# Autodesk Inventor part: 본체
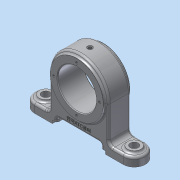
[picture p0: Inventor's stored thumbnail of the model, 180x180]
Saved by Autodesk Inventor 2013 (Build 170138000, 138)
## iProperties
Created: 2019-05
Part Number: 본체
Material: 알루미늄 6061
Document SubType Name: Modeling
Designer: dgall
Density: 2.71 g/cm^3
Mass: 457.09 g
Surface Area: 318.147 cm^2
Volume: 168.668 cm^3
Author: dgall
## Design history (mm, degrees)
sketch "스케치1"
  geometry: L1 (0, 0)-(0, 60); C1 r 40 at (0, 60)
  constraints: 2 end point, 1 centre point, 1 coincident, 1 vertical
  dimensions: "d0" = 60 distance of L1.start L1.end; "d1" = 80 diameter of C1
extrude "돌출1" new body sketch "스케치1" stored distance "d2" = 30; taper "d3" = 0 deg
sketch "스케치2"
  geometry: L1 (0, -40)-(60, -40); L2 (0, 40)-(60, 40); L3 (60, 40)-(60, -40); L4 (60, 0)-(60, 75); L5 (60, 75)-(48, 75); L6 (48, 75)-(48, 40); L7 (60, 0)-(60, -75); L8 (60, -75)-(48, -75); L9 (48, -75)-(48, -40); A1 r 40 centre (0, 0) between (0, -40) and (0, 40) reference
  constraints: 18 end point, 4 perpendicular, 2 parallel, 2 point on circle, 2 point on line, 2 tangent, 1 collinear, 1 horizontal
  dimensions: "d4" = 60 distance of L1.start L1.end; "d5" = 60 distance of L2.start L2.end; "d6" = 75 distance of L4.start L4.end; "d7" = 12 distance of L4.end L5.end; "d8" = 75 distance of L4.start L7.end; "d9" = 12 distance of L7.end L8.end
extrude "돌출2" join sketch "스케치2" distance "d10" = 30; taper "d11" = 0 deg
fillet "모깎기1" dims "d12" = 15
fillet "모깎기2" dims "d13" = 15
sketch "스케치3"
  geometry: C1 r 9 at (15, -20); A1 r 15 centre (15, -20) between (0, -20) and (30, -20) reference; 1 further point
  constraints: 1 centre point, 1 coincident
  dimensions: "d14" = 18 diameter of C1
extrude "돌출3" join sketch "스케치3" distance "d16" = 3; taper "d17" = 0 deg
sketch "스케치4"
  geometry: C1 r 9 at (15, 20); A1 r 15 centre (15, 20) between (30, 20) and (0, 20) reference; 1 further point
  constraints: 1 centre point, 1 coincident
  dimensions: "d18" = 18 diameter of C1
extrude "돌출4" join sketch "스케치4" distance "d20" = 3; taper "d21" = 0 deg
fillet "모깎기3" dims "d22" = 3
fillet "모깎기4" dims "d23" = 3
fillet "모깎기5" dims "d24" = 6
fillet "모깎기6" dims "d25" = 3
sketch "스케치5"
  geometry: C1 r 9 at (0, 0) reference; C2 r 9 at (0, 120) reference; 1 further point
hole "구멍1" sketch "스케치5" at (0, 0), (0, 120) diameter "d26" = 11; stored, may be unused: countersink angle "d30" = 90 deg, drill point angle "d32" = 0 deg; dims "d27" = 6, "d28" = 4, "d29" = 2, "d31" = 20
sketch "스케치6"
  geometry: L1 (0, -60)-(0, 60) reference; L2 (0, 0)-(0, -36); L3 (0, -36)-(-4, -36); L4 (0, 0)-(0, 36); L5 (0, 36)-(-4, 36); L6 (0, 0)-(-10, 0); L7 (-10, 0)-(-10, -30); L8 (-10, -30)-(-4, -30); L9 (-4, -30)-(-4, -36); L10 (-10, 0)-(-10, 30); L11 (-10, 30)-(-4, 30); L12 (-4, 30)-(-4, 36)
  constraints: 22 end point, 4 perpendicular, 3 parallel, 2 point on line
  dimensions: "d33" = 36 distance of L2.start L2.end; "d34" = 4 distance of L2.end L3.end; "d35" = 36 distance of L2.start L4.end; "d36" = 4 distance of L4.end L5.end; "d37" = 10 distance of L2.start L6.end; "d38" = 30 distance of L6.end L7.end; "d39" = 6 distance of L7.end L8.end; "d40" = 30 distance of L6.end L10.end; "d41" = 6 distance of L10.end L11.end
extrude "돌출5" cut sketch "스케치6" stored distance "d42" = 3; taper "d43" = 0 deg
fillet "모깎기7" dims "d44" = 3
fillet "모깎기8" dims "d45" = 3
node "작업 평면1"
sketch "스케치7"
  geometry: L1 (-4, -33)-(-7, -33) reference; L2 (-4, -33)-(-4, -36) reference; L3 (-4, -36)-(0, -36) reference; L4 (0, -36)-(0, -60) reference; L5 (-9, -60)-(0, -60) reference; L6 (-9, -46)-(-9, -60) reference; L7 (-60, -37)-(-18, -37) reference; L8 (-18, 37)-(-60, 37) reference; L9 (-9, 60)-(-9, 46) reference; L10 (0, 60)-(-9, 60) reference; L11 (0, 60)-(0, 36) reference; L12 (0, 36)-(-4, 36) reference; L13 (-4, 36)-(-4, 33) reference; L14 (-7, 33)-(-4, 33) reference; L15 (-13, -27)-(-13, 27) reference; L16 (-18, 37)-(-60, 37) reference; L17 (-18, -40)-(-60, -40) reference; C1 r 36 at (-60, 0); A1 r 9 centre (-18, -46) between (-9, -46) and (-9.719, -42.474) reference; A2 r 37 centre (-60, 0) between (-60, 37) and (-60, -37) reference; A3 r 9 centre (-18, 46) between (-9.719, 42.474) and (-9, 46) reference; A4 r 6 centre (-7, 27) between (-7, 33) and (-13, 27) reference; A5 r 6 centre (-7, -27) between (-13, -27) and (-7, -33) reference; A6 r 40 centre (-60, 0) between (-60, 40) and (-60, -40) reference; 1 further point
  constraints: 1 centre point, 1 coincident, 2 other
  dimensions: "d46" = 72 diameter of C1
extrude "돌출6" join sketch "스케치7" stored distance "d48" = 36; taper "d49" = 0 deg
fillet "모깎기9" dims "d50" = 3
sketch "스케치8"
  geometry: C1 r 26 at (-60, 0); A1 r 36 centre (-60, 0) between (-48.62, 34.154) and (-48.62, -34.154) reference; 1 further point
  constraints: 1 centre point, 1 coincident
  dimensions: "d51" = 52 diameter of C1
extrude "돌출7" cut sketch "스케치8" stored distance "d53" = 36; taper "d54" = 0 deg
node "작업 평면2"
sketch "스케치10"
  geometry: L1 (-12, -100)-(-12, -20) reference; L2 (-12, -100)-(12, -100) reference; L3 (12, -20)-(12, -100) reference; L4 (-12, -20)-(12, -20) reference; 1 further point
hole "구멍3" sketch "스케치10" at (0, -60) diameter "d71" = 4.917; stored, may be unused: countersink angle "d75" = 82 deg, drill point angle "d77" = 118 deg; dims "d72" = 8, "d73" = 7, "d74" = 1, "d76" = 10
sketch "스케치11"
  geometry: C1 r 1 at (0, -60); 1 further point
  constraints: 1 centre point, 1 coincident
  dimensions: "d78" = 2 diameter of C1
extrude "돌출8" cut sketch "스케치11" stored distance "d80" = 36; taper "d81" = 0 deg
sketch "스케치12"
  geometry: L1 (-10, -27)-(-10, 27) reference; 3 further points
  constraints: 1 coincident, 1 other
  dimensions: "d96" = 7 distance from line of L1 point (-17, 0)
feature "엠보싱1" sketch "스케치12" dims "d0" = 60, "d1" = 80, "d84" = 0.5, "d85" = 0
sketch "스케치13"
  geometry: L1 (-61.621, 0)-(-86, 0); C1 r 1.5 at (-86, 0); 2 further points
  constraints: 2 end point, 1 centre point, 1 coincident, 1 horizontal, 1 horizontal alignment, 1 other
  dimensions: "d86" = 3 diameter of C1
extrude "돌출9" cut sketch "스케치13" stored distance "d88" = 36; taper "d89" = 0 deg
chamfer "모따기2" distance "d90" = 1; stored, may be unused: second distance "d91" = 2, angle "d92" = 45 deg
chamfer "모따기3" distance "d93" = 1; stored, may be unused: second distance "d94" = 2, angle "d95" = 45 deg
sketch "스케치14" dims "d97" = 62
  geometry: L1 (-60, 0)-(-91, 0); A1 r 36 centre (-60, 0) between (-48.62, 34.154) and (-48.62, -34.154) reference; 2 further points
  constraints: 2 coincident, 2 end point, 1 horizontal, 1 horizontal alignment, 2 other
hole "구멍4" sketch "스케치14" at (-91, 0) diameter "d99" = 3.242; stored, may be unused: countersink angle "d103" = 82 deg, drill point angle "d105" = 118 deg; dims "d100" = 6, "d101" = 7, "d102" = 1, "d104" = 8
node "솔리드1"
pattern_circular "원형 패턴2" dims angle "d107" = 360 deg
mirror "대칭2"
node "투영된 루프1"
node "투영된 루프2"
node "투영된 루프3"
